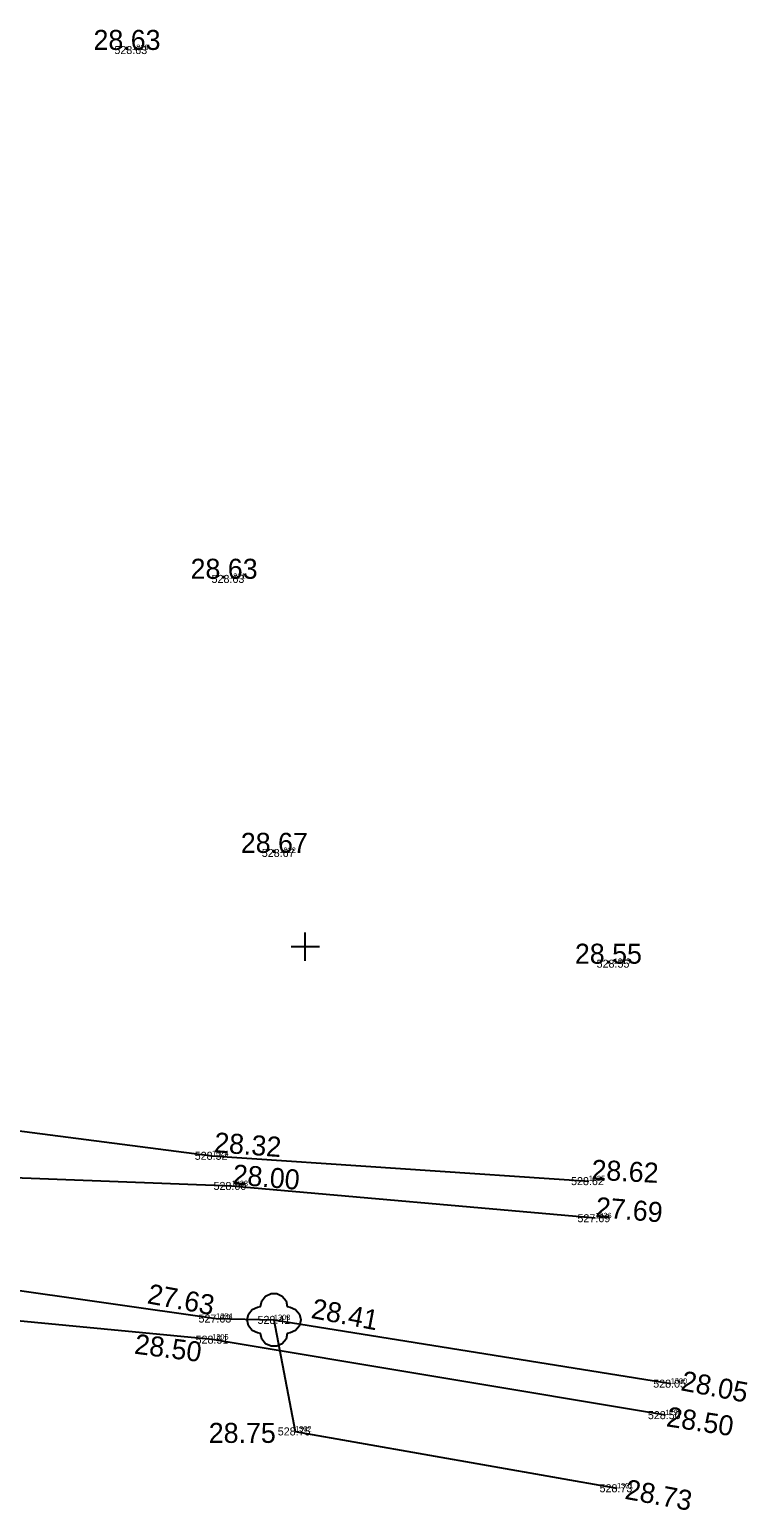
# Model space of a CAD drawing. Extents: x -866693 to -866303, y -1041966 to -1040244.
# Drawn here: x -866460.3 to -866433.4, y -1041771.1 to -1041715.6 of the extents above; entities that cross this region are included whole.
import ezdxf

# ---------------------------------------------------------------- set-up
doc = ezdxf.new("R2010")
doc.units = 0
for name, color, linetype in [('11 hrana lesa _pole _porostu', 7, 'Continuous'), ('12 potok _kanál-břeh', 7, 'Continuous'), ('13 potok _kanál-dno', 7, 'Continuous'), ('6 bod terénu', 7, 'Continuous'), ('60 strom bez rozlišení', 7, 'Continuous'), ('Bod', 7, 'Continuous'), ('Nadmořská výška', 7, 'Continuous'), ('Nadmořská výška_tisk', 7, 'Continuous'), ('Síť křížek', 7, 'Continuous'), ('Číslo bodu', 7, 'Continuous')]:
    doc.layers.add(name, color=color, linetype=linetype)

msp = doc.modelspace()

# ---------------------------------------------------------------- linework, layer by layer
at = {"layer": '11 hrana lesa _pole _porostu'}
for p, q in [((-866451.172, -1041763.994), (-866450.378, -1041768.171)), ((-866450.378, -1041768.171), (-866438.327, -1041770.302))]:
    msp.add_line(p, q, dxfattribs=at)
at = {"layer": '12 potok _kanál-břeh'}
for p, q in [((-866463.982, -1041756.472), (-866453.489, -1041757.844)), ((-866453.489, -1041757.844), (-866439.386, -1041758.787)), ((-866453.486, -1041764.725), (-866469.001, -1041763.241)), ((-866436.514, -1041767.557), (-866453.486, -1041764.725))]:
    msp.add_line(p, q, dxfattribs=at)
at = {"layer": '13 potok _kanál-dno'}
for p, q in [((-866452.757, -1041758.973), (-866464.03, -1041758.542)), ((-866439.145, -1041760.178), (-866452.757, -1041758.973)), ((-866469.037, -1041761.703), (-866453.338, -1041763.941)), ((-866453.338, -1041763.941), (-866451.172, -1041763.994)), ((-866451.172, -1041763.994), (-866436.314, -1041766.375))]:
    msp.add_line(p, q, dxfattribs=at)
at = {"layer": '6 bod terénu'}
for p, q in [((-866456.485, -1041716.395), (-866456.485, -1041716.395)), ((-866452.85, -1041736.215), (-866452.85, -1041736.215)), ((-866450.966, -1041746.487), (-866450.966, -1041746.487)), ((-866438.442, -1041750.642), (-866438.442, -1041750.642))]:
    msp.add_line(p, q, dxfattribs=at)
at = {"layer": '60 strom bez rozlišení'}
msp.add_lwpolyline([(-866450.172, -1041763.994), (-866450.221, -1041764.211), (-866450.361, -1041764.385), (-866450.561, -1041764.481), (-866450.672, -1041764.494), (-866450.721, -1041764.711), (-866450.861, -1041764.885), (-866451.061, -1041764.981), (-866451.283, -1041764.981), (-866451.483, -1041764.885), (-866451.623, -1041764.711), (-866451.672, -1041764.494), (-866451.783, -1041764.481), (-866451.983, -1041764.385), (-866452.123, -1041764.211), (-866452.172, -1041763.994), (-866452.123, -1041763.777), (-866451.983, -1041763.603), (-866451.783, -1041763.507), (-866451.672, -1041763.494), (-866451.623, -1041763.277), (-866451.483, -1041763.103), (-866451.283, -1041763.007), (-866451.061, -1041763.007), (-866450.861, -1041763.103), (-866450.721, -1041763.277), (-866450.672, -1041763.494), (-866450.561, -1041763.507), (-866450.361, -1041763.603), (-866450.221, -1041763.777)], close=True, dxfattribs=at)
msp.add_lwpolyline([(-866451.197, -1041763.994), (-866451.172, -1041763.994), (-866451.147, -1041763.994)], dxfattribs=at)
at = {"layer": 'Bod'}
for p, q in [((-866453.489, -1041757.844), (-866453.489, -1041757.844)), ((-866452.757, -1041758.973), (-866452.757, -1041758.973)), ((-866439.386, -1041758.787), (-866439.386, -1041758.787)), ((-866439.145, -1041760.178), (-866439.145, -1041760.178)), ((-866453.338, -1041763.941), (-866453.338, -1041763.941)), ((-866451.172, -1041763.994), (-866451.172, -1041763.994)), ((-866453.486, -1041764.725), (-866453.486, -1041764.725)), ((-866436.314, -1041766.375), (-866436.314, -1041766.375)), ((-866436.514, -1041767.557), (-866436.514, -1041767.557)), ((-866450.378, -1041768.171), (-866450.378, -1041768.171)), ((-866438.327, -1041770.302), (-866438.327, -1041770.302))]:
    msp.add_line(p, q, dxfattribs=at)
at = {"layer": 'Síť křížek'}
for p, q in [((-866450, -1041750.53), (-866450, -1041749.47)), ((-866450.53, -1041750), (-866449.47, -1041750))]:
    msp.add_line(p, q, dxfattribs=at)

# ---------------------------------------------------------------- texts
at = {"layer": 'Nadmořská výška'}
for s, p in [('528.63', (-866457.148, -1041716.55)), ('528.63', (-866453.508, -1041736.37)), ('528.67', (-866451.628, -1041746.64)), ('528.55', (-866439.09, -1041750.79)), ('528.32', (-866454.14, -1041757.99)), ('528.00', (-866453.435, -1041759.12)), ('528.62', (-866440.048, -1041758.94)), ('527.69', (-866439.809, -1041760.33)), ('527.63', (-866453.998, -1041764.09)), ('528.41', (-866451.787, -1041764.14)), ('528.51', (-866454.107, -1041764.88)), ('528.05', (-866436.972, -1041766.53)), ('528.50', (-866437.172, -1041767.71)), ('528.75', (-866451.03, -1041768.32)), ('528.73', (-866438.98, -1041770.45))]:
    msp.add_text(s, height=0.3, dxfattribs=at).set_placement(p)
at = {"layer": 'Nadmořská výška_tisk'}
for s, p in [('28.63', (-866457.929, -1041716.395)), ('28.63', (-866454.294, -1041736.215)), ('28.67', (-866452.413, -1041746.487)), ('28.55', (-866439.903, -1041750.642)), ('28.75', (-866453.614, -1041768.6))]:
    msp.add_text(s, height=0.75, dxfattribs=at).set_placement(p)
for s, rotation, p in [('28.32', 355.779, (-866453.43, -1041757.705)), ('28.62', 357.126, (-866439.297, -1041758.732)), ('28.00', 355.1226, (-866452.744, -1041758.905)), ('27.69', 355.1701, (-866439.151, -1041760.13)), ('27.63', 349.5285, (-866455.95, -1041763.364)), ('28.41', 349.1548, (-866449.813, -1041763.913)), ('28.50', 352.7217, (-866456.426, -1041765.253)), ('28.05', 349.2442, (-866435.97, -1041766.624)), ('28.50', 351.3653, (-866436.509, -1041767.975)), ('28.73', 349.4826, (-866438.065, -1041770.691))]:
    msp.add_text(s, height=0.75, rotation=rotation, dxfattribs=at).set_placement(p)
at = {"layer": 'Číslo bodu'}
for s, p in [('1216', (-866456.485, -1041716.395)), ('1221', (-866452.85, -1041736.215)), ('1222', (-866450.966, -1041746.487)), ('1223', (-866438.442, -1041750.642)), ('1324', (-866453.489, -1041757.844)), ('1225', (-866439.386, -1041758.787)), ('1323', (-866452.757, -1041758.973)), ('1226', (-866439.145, -1041760.178)), ('1304', (-866453.338, -1041763.941)), ('1303', (-866451.172, -1041763.994)), ('1305', (-866453.486, -1041764.725)), ('1300', (-866436.314, -1041766.375)), ('1299', (-866436.514, -1041767.557)), ('1302', (-866450.378, -1041768.171)), ('1301', (-866438.327, -1041770.302))]:
    msp.add_text(s, height=0.2, dxfattribs=at).set_placement(p)

doc.saveas('drawing.dxf')
